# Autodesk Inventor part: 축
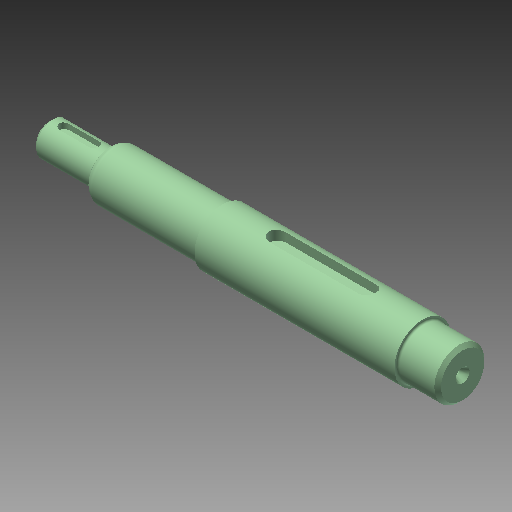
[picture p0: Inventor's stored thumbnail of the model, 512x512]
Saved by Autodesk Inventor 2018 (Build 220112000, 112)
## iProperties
Created: 2024-01
Part Number: 축
Material: 강철, 탄소
Document SubType Name: Modeling
Designer: mdu-01
Density: 1 g/cm^3
Appearance: 기본값(1)
Author: mdu-01
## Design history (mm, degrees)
sketch "스케치1"
  geometry: L1 (0, 0)-(118.751, 0); L2 (124, 2.125)-(124, 6.5); L3 (123, 7.5)-(112.6, 7.5); L4 (112, 8.1)-(112, 8.5); L5 (112, 8.5)-(52, 8.5); L6 (52, 8.5)-(52, 8.1); L7 (51.4, 7.5)-(20.268, 7.5); L8 (18, 5.923)-(18, 5); L9 (18, 5)-(1, 5); L10 (0, 4)-(0, 0); L11 (124, 2.125)-(122.051, 1); L12 (122.051, 1)-(119.329, 1); L13 (119.329, 1)-(118.751, 0); L14 (124, 6.5)-(123, 7.5); L15 (1, 5)-(0, 4); L16 (18.5, 6.789)-(19.268, 7.232); A1 r 0.6 centre (51.4, 8.1) between (51.4, 7.5) and (52, 8.1); A2 r 0.6 centre (112.6, 8.1) between (112, 8.1) and (112.6, 7.5); A3 r 2 centre (20.268, 5.5) between (20.268, 7.5) and (19.268, 7.232); A4 r 1 centre (19, 5.923) between (18.5, 6.789) and (18, 5.923); 3 further points
  constraints: 32 end point, 8 parallel, 8 point on circle, 8 tangent, 6 point on line, 4 centre point, 2 horizontal, 1 collinear, 1 equal radius, 1 perpendicular
  dimensions: "d0" = 2 diameter of L12 L1; "d2" = 4.25 diameter of L2.start L1; "d3" = 30 deg angle of L1 L11; "d4" = 60 deg angle of L1 L13; "d5" = 3.3 horizontal distance of L1.end L11.end; "d6" = 124 distance between parallel lines of L10 L2; "d7" = 12 distance between parallel lines of L4 L2; "d8" = 34 distance between parallel lines of L6 L8; "d9" = 18 distance between parallel lines of L8 L10; "d10" = 10 diameter of L9 L1; "d11" = 15 diameter of L7 L1; "d12" = 17 diameter of L5 L1; "d13" = 0.6 radius of A1; "d14" = 1 distance of L2.end point (124, 7.5); "d15" = 1 distance of L3.start point (124, 7.5) (= d14); "d16" = 1 distance of L9.end point (0, 5) (= d14); "d17" = 1 distance of L10.start point (0, 5) (= d16); "d18" = 13 diameter of point (18, 6.5) L1; "d19" = 30 deg angle of L7 L16; "d20" = 2 radius of A3; "d21" = 1 radius of A4
revolve "회전1" sketch "스케치1" stored, may be unused: angle "d22" = 90 deg
hole "구멍1" diameter "d25" = 3.242; stored, may be unused: countersink angle "d29" = 90 deg, drill point angle "d31" = 118 deg; dims "d23" = 10, "d24" = 10, "d26" = 8, "d27" = 4, "d28" = 2, "d30" = 10
sketch "스케치2"
  geometry: L1 (0, -1.621)-(0, 1.621) reference; L2 (0, -4)-(0, 4) reference; L3 (0, 0)-(4.59, 0); L4 (4.59, 0)-(0, 2.65); L5 (0, 2.65)-(0, 0)
  constraints: 6 end point, 1 collinear, 1 perpendicular, 1 point on line
  dimensions: "d32" = 30 deg angle of L3 L4; "d33" = 5.3 diameter of L4.end L3
revolve "회전2" sketch "스케치2" stored, may be unused: angle "d35" = 90 deg
sketch "스케치3"
  geometry: L1 (18, -5)-(18, 5) reference; L2 (1, -5)-(1, 5) reference; L3 (3, 5)-(15, 5); L4 (15, 5)-(15, 3.2); L5 (15, 3.2)-(3, 3.2); L6 (3, 3.2)-(3, 5); 1 further point
  constraints: 8 end point, 2 parallel, 1 horizontal, 1 perpendicular, 1 point on line
  dimensions: "d36" = 3 distance between parallel lines of L4 L1; "d37" = 12 distance between parallel lines of L6 L4; "d38" = 1.8 distance between parallel lines of L5 L3
extrude "돌출1" cut sketch "스케치3" stored distance "d39" = 3; taper "d40" = 0 deg
fillet "모깎기1"
fillet "모깎기2"
sketch "스케치4"
  geometry: L1 (112, -8.5)-(112, 8.5) reference; L2 (52, -8.5)-(52, 8.5) reference; L3 (66, 8.5)-(98, 8.5); L4 (98, 8.5)-(98, 5.5); L5 (98, 5.5)-(66, 5.5); L6 (66, 5.5)-(66, 8.5); 1 further point
  constraints: 8 end point, 2 parallel, 1 horizontal, 1 perpendicular, 1 point on line
  dimensions: "d41" = 14 distance between parallel lines of L6 L2; "d42" = 32 distance between parallel lines of L4 L6; "d43" = 3 distance between parallel lines of L5 L3
extrude "돌출2" cut sketch "스케치4" stored distance "d44" = 5; taper "d45" = 0 deg
fillet "모깎기3"
fillet "모깎기4"
node "솔리드1"
node "투영된 루프1"
node "투영된 루프2"
node "투영된 루프3"
